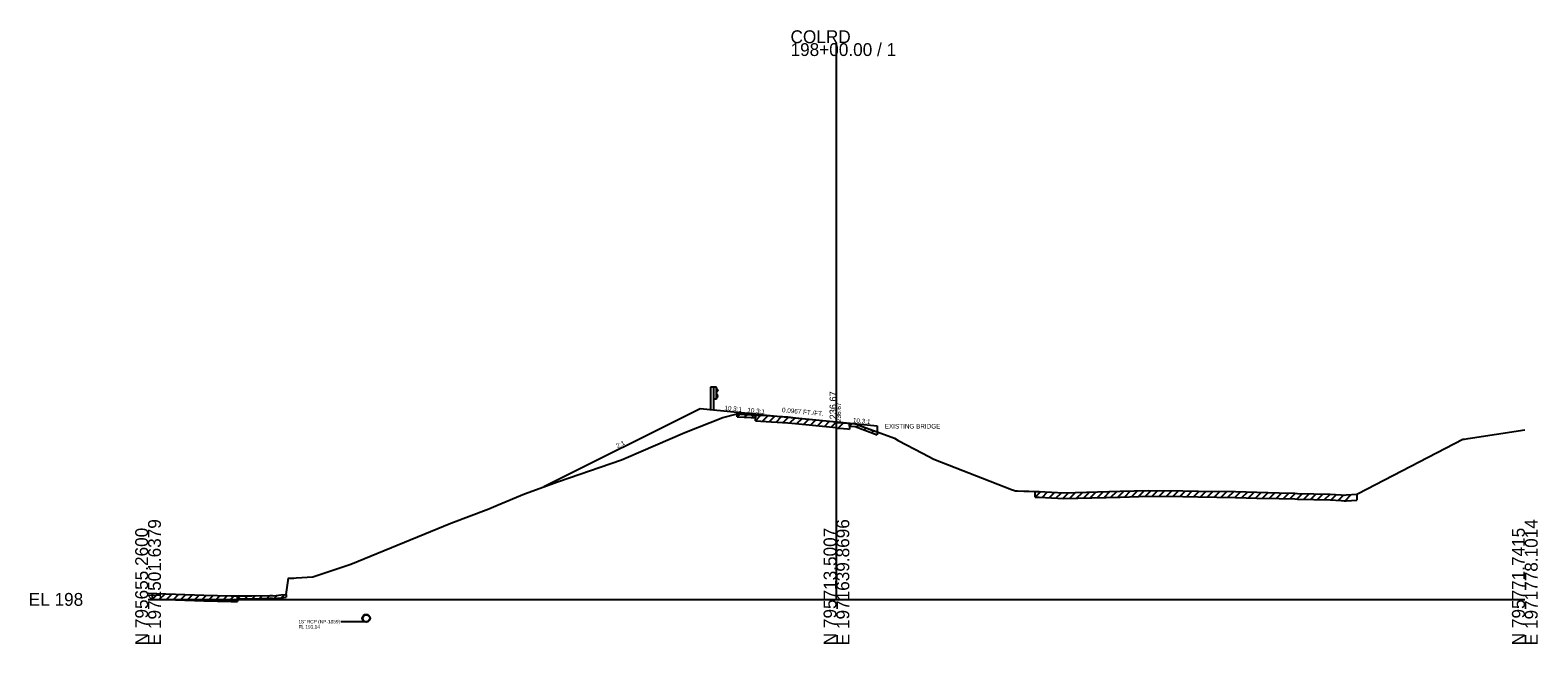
# Model space of a CAD drawing. Extents: x -26 to 1971520, y -10 to 796285.
# Drawn here: x -25.7 to 302.8, y 2990.3 to 3124.1 of the extents above; entities that cross this region are included whole.
import ezdxf

# ---------------------------------------------------------------- set-up
doc = ezdxf.new("R2010")
doc.units = 0
for name, color, linetype in [('RD_GPK_XS_Cell', 7, 'Continuous'), ('RD_XS_Base', 7, 'Continuous'), ('RD_XS_Box', 7, 'Continuous'), ('RD_XS_EarthShd', 7, 'Continuous'), ('RD_XS_ExGround', 7, 'Continuous'), ('RD_XS_ExPaveRet', 7, 'Continuous'), ('RD_XS_GR', 7, 'Continuous'), ('RD_XS_Misc_Line', 7, 'Continuous'), ('RD_XS_Pave', 7, 'Continuous'), ('RD_XS_PaveOvlay', 7, 'Continuous'), ('RD_XS_PaveShd', 7, 'Continuous'), ('RD_XS_Pipe', 7, 'Continuous'), ('RD_XS_TieSlope', 7, 'Continuous'), ('RD_XS_TX_Elev_EX', 7, 'Continuous'), ('RD_XS_TX_Elev_PR', 7, 'Continuous'), ('RD_XS_TX_Notes', 7, 'Continuous'), ('RD_XS_TX_Profile', 7, 'Continuous'), ('RD_XS_TX_ShdSlope', 7, 'Continuous'), ('RD_XS_TX_Slope', 7, 'Continuous')]:
    doc.layers.add(name, color=color, linetype=linetype)

msp = doc.modelspace()

# ---------------------------------------------------------------- linework, layer by layer
at = {"layer": 'RD_GPK_XS_Cell'}
for p, q in [((150, 3000), (150, 3121.24)), ((0, 3000), (150, 3000)), ((150, 3000), (300, 3000))]:
    msp.add_line(p, q, dxfattribs=at)
at = {"layer": 'RD_XS_Base'}
msp.add_line((128.38, 3040.41), (128.38, 3040.76), dxfattribs=at)
at = {"layer": 'RD_XS_Box'}
msp.add_line((158.84, 3037.81), (158.84, 3036.51), dxfattribs=at)
at = {"layer": 'RD_XS_EarthShd'}
msp.add_line((128.38, 3040.76), (120.27, 3041.54), dxfattribs=at)
at = {"layer": 'RD_XS_ExGround'}
msp.add_lwpolyline([(0, 3001.37), (3.84, 3001.22), (5.95, 3001.14), (12.14, 3000.94), (18.12, 3000.76), (19.38, 3000.76), (22.61, 3000.77), (26.53, 3000.85), (27.04, 3000.86), (27.44, 3000.8), (28.93, 3000.97), (30.09, 3001.08), (30.63, 3004.65), (31.75, 3004.66), (32.26, 3004.69), (35.94, 3004.94), (44.16, 3007.7), (65.97, 3016.65), (74.26, 3019.76), (76.27, 3020.59), (82.03, 3022.98), (89.47, 3025.72), (103.18, 3030.42), (104.21, 3030.87), (116.97, 3036.38), (125.21, 3039.68), (128.38, 3040.41), (131.41, 3040.24), (132.69, 3040.17), (133.52, 3040.12), (139.38, 3039.76), (141.08, 3039.59), (149.95, 3038.71), (150.11, 3038.59), (150.64, 3038.56), (152.42, 3038.4), (154.08, 3038.27), (162.64, 3035.11), (163.44, 3034.66), (168.74, 3031.87), (171.22, 3030.57), (188.17, 3023.92), (188.99, 3023.64), (189.43, 3023.63), (190.85, 3023.6), (191.89, 3023.58), (193.32, 3023.54), (194.17, 3023.51), (199.52, 3023.22), (211.8, 3023.56), (217.94, 3023.74), (225.46, 3023.67), (228.84, 3023.61), (236.95, 3023.48), (241.58, 3023.34), (246.47, 3023.21), (249.88, 3023.14), (250.45, 3023.11), (257.62, 3022.96), (259.97, 3022.78), (260.63, 3022.73), (261.09, 3022.76), (263.41, 3022.91), (263.71, 3023.08), (286.51, 3034.9), (286.85, 3034.93), (287.64, 3035.06), (300, 3036.97)], dxfattribs=at)
at = {"layer": 'RD_XS_ExPaveRet'}
for p, q in [((128.38, 3039.79), (128.38, 3040.41)), ((128.38, 3039.79), (131.41, 3039.61)), ((131.41, 3039.61), (132.38, 3039.56)), ((132.38, 3038.94), (132.38, 3040.19)), ((132.38, 3040.19), (132.38, 3039.56)), ((132.38, 3038.94), (132.69, 3038.92)), ((132.69, 3038.92), (133.52, 3038.87)), ((133.52, 3038.87), (139.38, 3038.51)), ((139.38, 3038.51), (141.08, 3038.34)), ((141.08, 3038.34), (149.95, 3037.46)), ((149.95, 3037.46), (150.11, 3037.34)), ((150.11, 3037.34), (150.64, 3037.31)), ((150.64, 3037.31), (152.42, 3037.15)), ((152.42, 3037.15), (152.84, 3037.12)), ((152.84, 3038.37), (152.84, 3037.12)), ((152.84, 3037.74), (152.84, 3038.37)), ((152.84, 3037.74), (154.08, 3037.65)), ((154.08, 3037.65), (158.84, 3035.89)), ((158.84, 3036.51), (158.84, 3035.89)), ((193.32, 3022.29), (193.32, 3023.54)), ((263.41, 3022.91), (263.41, 3021.66)), ((193.32, 3022.29), (194.17, 3022.26)), ((194.17, 3022.26), (199.52, 3021.97)), ((199.52, 3021.97), (211.8, 3022.31)), ((211.8, 3022.31), (217.94, 3022.49)), ((217.94, 3022.49), (225.46, 3022.42)), ((225.46, 3022.42), (228.84, 3022.36)), ((228.84, 3022.36), (236.95, 3022.23)), ((236.95, 3022.23), (241.58, 3022.09)), ((241.58, 3022.09), (246.47, 3021.96)), ((246.47, 3021.96), (249.88, 3021.89)), ((249.88, 3021.89), (250.45, 3021.86)), ((250.45, 3021.86), (257.62, 3021.71)), ((257.62, 3021.71), (259.97, 3021.53)), ((259.97, 3021.53), (260.63, 3021.48)), ((260.63, 3021.48), (261.09, 3021.51)), ((261.09, 3021.51), (263.41, 3021.66)), ((1, 3000.08), (1, 3001.33)), ((1, 3000.08), (3.84, 2999.97)), ((3.84, 2999.97), (5.95, 2999.89)), ((5.95, 2999.89), (12.14, 2999.69)), ((12.14, 2999.69), (18.12, 2999.51)), ((18.12, 2999.51), (19.38, 2999.51)), ((19.38, 2999.51), (19.49, 2999.51)), ((19.49, 3000.76), (19.49, 2999.51)), ((19.49, 3000.14), (19.49, 3000.76)), ((19.49, 3000.14), (22.61, 3000.14)), ((22.61, 3000.14), (26.53, 3000.23)), ((26.53, 3000.23), (27.04, 3000.24)), ((27.04, 3000.24), (27.44, 3000.17)), ((27.44, 3000.17), (28.93, 3000.35)), ((28.93, 3000.35), (30.09, 3000.46)), ((30.09, 3001.08), (30.09, 3000.46))]:
    msp.add_line(p, q, dxfattribs=at)
at = {"layer": 'RD_XS_GR'}
for p, q in [((123.2, 3046.23), (122.54, 3046.23)), ((122.54, 3046.23), (122.54, 3041.18)), ((123.87, 3046.23), (123.2, 3046.23)), ((123.2, 3046.23), (123.2, 3041.29)), ((123.87, 3043.67), (123.87, 3046.23)), ((123.87, 3046.07), (124.14, 3045.63)), ((124.14, 3045.52), (123.87, 3045.08)), ((124.14, 3045.63), (124.14, 3045.52)), ((123.87, 3043.67), (123.2, 3043.67)), ((124.14, 3044.38), (123.87, 3044.82)), ((123.87, 3043.83), (124.14, 3044.27)), ((124.14, 3044.27), (124.14, 3044.38))]:
    msp.add_line(p, q, dxfattribs=at)
at = {"layer": 'RD_XS_Misc_Line'}
for p, q in [((128.38, 3039.79), (129, 3040.38)), ((129.97, 3039.7), (130.59, 3040.28)), ((131.56, 3039.61), (132.19, 3040.2)), ((132.38, 3038.94), (133.56, 3040.12)), ((133.88, 3038.85), (135.05, 3040.03)), ((135.38, 3038.76), (136.55, 3039.93)), ((136.88, 3038.66), (138.05, 3039.84)), ((138.38, 3038.57), (139.55, 3039.74)), ((139.88, 3038.46), (141.01, 3039.6)), ((141.38, 3038.31), (142.51, 3039.45)), ((142.88, 3038.16), (144.01, 3039.3)), ((144.38, 3038.01), (145.51, 3039.15)), ((145.88, 3037.86), (147.01, 3039)), ((147.38, 3037.72), (148.51, 3038.85)), ((148.88, 3037.57), (149.99, 3038.68)), ((150.38, 3037.32), (151.53, 3038.48)), ((152.84, 3037.74), (153.45, 3038.32)), ((154.43, 3037.52), (154.9, 3037.97)), ((156.02, 3036.93), (156.5, 3037.38)), ((157.61, 3036.34), (158.09, 3036.79)), ((193.32, 3022.29), (194.52, 3023.49)), ((194.82, 3022.22), (196.01, 3023.41)), ((196.32, 3022.14), (197.51, 3023.33)), ((197.82, 3022.06), (199.01, 3023.25)), ((199.32, 3021.98), (200.59, 3023.25)), ((200.82, 3022.01), (202.11, 3023.29)), ((202.32, 3022.05), (203.61, 3023.33)), ((203.82, 3022.09), (205.11, 3023.38)), ((205.32, 3022.13), (206.61, 3023.42)), ((206.82, 3022.17), (208.11, 3023.46)), ((208.32, 3022.21), (209.61, 3023.5)), ((209.82, 3022.26), (211.11, 3023.54)), ((211.32, 3022.3), (212.61, 3023.58)), ((212.82, 3022.34), (214.11, 3023.63)), ((214.32, 3022.38), (215.61, 3023.67)), ((215.82, 3022.43), (217.11, 3023.71)), ((217.32, 3022.47), (218.59, 3023.73)), ((218.82, 3022.48), (220.06, 3023.72)), ((220.32, 3022.47), (221.56, 3023.71)), ((221.82, 3022.45), (223.06, 3023.69)), ((223.32, 3022.44), (224.56, 3023.68)), ((224.82, 3022.43), (226.06, 3023.66)), ((226.32, 3022.41), (227.55, 3023.63)), ((227.82, 3022.38), (229.05, 3023.6)), ((229.32, 3022.35), (230.56, 3023.58)), ((230.82, 3022.33), (232.06, 3023.56)), ((232.32, 3022.3), (233.56, 3023.53)), ((233.82, 3022.28), (235.06, 3023.51)), ((235.32, 3022.26), (236.56, 3023.49)), ((236.82, 3022.23), (238.04, 3023.45)), ((238.32, 3022.19), (239.54, 3023.4)), ((239.82, 3022.14), (241.04, 3023.35)), ((241.32, 3022.09), (242.54, 3023.31)), ((242.82, 3022.06), (244.04, 3023.27)), ((244.32, 3022.02), (245.54, 3023.24)), ((245.82, 3021.98), (247.04, 3023.2)), ((247.32, 3021.94), (248.55, 3023.17)), ((248.82, 3021.91), (250.04, 3023.13)), ((250.32, 3021.87), (251.55, 3023.09)), ((251.82, 3021.83), (253.05, 3023.06)), ((253.32, 3021.8), (254.55, 3023.03)), ((254.82, 3021.77), (256.05, 3022.99)), ((256.32, 3021.74), (257.55, 3022.96)), ((257.82, 3021.7), (258.99, 3022.86)), ((259.32, 3021.58), (260.49, 3022.75)), ((260.82, 3021.5), (262.16, 3022.83)), ((1, 3000.08), (2.2, 3001.28)), ((2.5, 3000.02), (3.7, 3001.22)), ((4, 2999.96), (5.2, 3001.16)), ((5.5, 2999.9), (6.71, 3001.11)), ((7, 2999.85), (8.21, 3001.06)), ((8.5, 2999.8), (9.71, 3001.02)), ((10, 2999.76), (11.21, 3000.97)), ((11.5, 2999.71), (12.71, 3000.92)), ((13, 2999.66), (14.21, 3000.88)), ((14.5, 2999.62), (15.71, 3000.83)), ((16, 2999.57), (17.21, 3000.78)), ((17.5, 2999.52), (18.73, 3000.76)), ((19.49, 3000.14), (20.15, 3000.76)), ((21.08, 3000.14), (21.74, 3000.77)), ((22.67, 3000.14), (23.35, 3000.78)), ((24.26, 3000.18), (24.94, 3000.82)), ((25.86, 3000.21), (26.53, 3000.85)), ((27.45, 3000.17), (28.2, 3000.89)), ((29.04, 3000.36), (29.78, 3001.05))]:
    msp.add_line(p, q, dxfattribs=at)
at = {"layer": 'RD_XS_Pave'}
msp.add_line((134, 3040.22), (150, 3038.67), dxfattribs=at)
at = {"layer": 'RD_XS_PaveOvlay'}
for p, q in [((128.38, 3040.41), (129.89, 3040.32)), ((129.89, 3040.32), (131.41, 3040.24)), ((131.41, 3040.24), (132.38, 3040.19)), ((132.38, 3040.19), (132.69, 3040.17)), ((132.69, 3040.17), (133.52, 3040.12)), ((133.52, 3040.12), (139.38, 3039.76)), ((139.38, 3039.76), (141.08, 3039.59)), ((141.08, 3039.59), (149.95, 3038.71)), ((149.95, 3038.71), (150.11, 3038.59)), ((150.11, 3038.59), (150.64, 3038.56)), ((150.64, 3038.56), (152.42, 3038.4)), ((152.42, 3038.4), (152.84, 3038.37)), ((152.84, 3038.37), (154.08, 3038.27)), ((154.08, 3038.27), (158.36, 3036.69)), ((158.36, 3036.69), (158.84, 3036.51))]:
    msp.add_line(p, q, dxfattribs=at)
at = {"layer": 'RD_XS_PaveShd'}
for p, q in [((134, 3040.22), (128.38, 3040.76)), ((150, 3038.67), (158.84, 3037.81))]:
    msp.add_line(p, q, dxfattribs=at)
at = {"layer": 'RD_XS_Pipe'}
msp.add_line((47.04, 2995.14), (42.04, 2995.14), dxfattribs=at)
for radius in [0.85, 0.75]:
    msp.add_circle((47.54, 2995.89), radius, dxfattribs=at)
at = {"layer": 'RD_XS_TieSlope'}
msp.add_line((120.27, 3041.54), (86.23, 3024.52), dxfattribs=at)

# ---------------------------------------------------------------- texts
at = {"layer": 'RD_GPK_XS_Cell'}
for s, p in [('COLRD', (140, 3121.24)), ('198+00.00 / 1', (140, 3118.44)), ('EL 198', (-26, 2998.6))]:
    msp.add_text(s, height=2.8, dxfattribs=at).set_placement(p)
for s, p in [('E 1971501.6379', (2.8, 2990)), ('E 1971639.8696', (152.8, 2990)), ('E 1971778.1014', (302.8, 2990)), ('N 795655.2600', (0, 2990)), ('N 795713.5007', (150, 2990)), ('N 795771.7415', (300, 2990))]:
    msp.add_text(s, height=2.8, rotation=90, dxfattribs=at).set_placement(p)
at = {"layer": 'RD_XS_Pipe'}
for s, p in [('18" RCP (NP-1859)', (32.78, 2994.77)), ('FL 193.14', (32.78, 2993.64))]:
    msp.add_text(s, height=0.75, dxfattribs=at).set_placement(p)
at = {"layer": 'RD_XS_TX_Elev_EX'}
msp.add_text('236.67', height=1, rotation=90, dxfattribs=at).set_placement((151, 3038.67))
at = {"layer": 'RD_XS_TX_Elev_PR'}
msp.add_text(' 236.67', height=1.5, rotation=90, dxfattribs=at).set_placement((150, 3038.67))
at = {"layer": 'RD_XS_TX_Notes'}
msp.add_text('EXISTING BRIDGE', height=1, dxfattribs=at).set_placement((160.53, 3037.24))
at = {"layer": 'RD_XS_TX_Profile'}
msp.add_text('10.3:1', height=1, rotation=354.4763, dxfattribs=at).set_placement((153.55, 3038.58))
at = {"layer": 'RD_XS_TX_ShdSlope'}
msp.add_text('10.3:1', height=1, rotation=354.4763, dxfattribs=at).set_placement((125.55, 3041.28))
at = {"layer": 'RD_XS_TX_Slope'}
for s, rotation, p in [('10.3:1', 354.4763, (130.55, 3040.8)), ('0.0967 FT./FT.', 354.4763, (138.1, 3040.82)), ('2:1', 26.565, (102.28, 3032.93))]:
    msp.add_text(s, height=1, rotation=rotation, dxfattribs=at).set_placement(p)

doc.saveas('drawing.dxf')
